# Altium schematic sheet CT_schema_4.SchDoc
size 205 x 258 mm
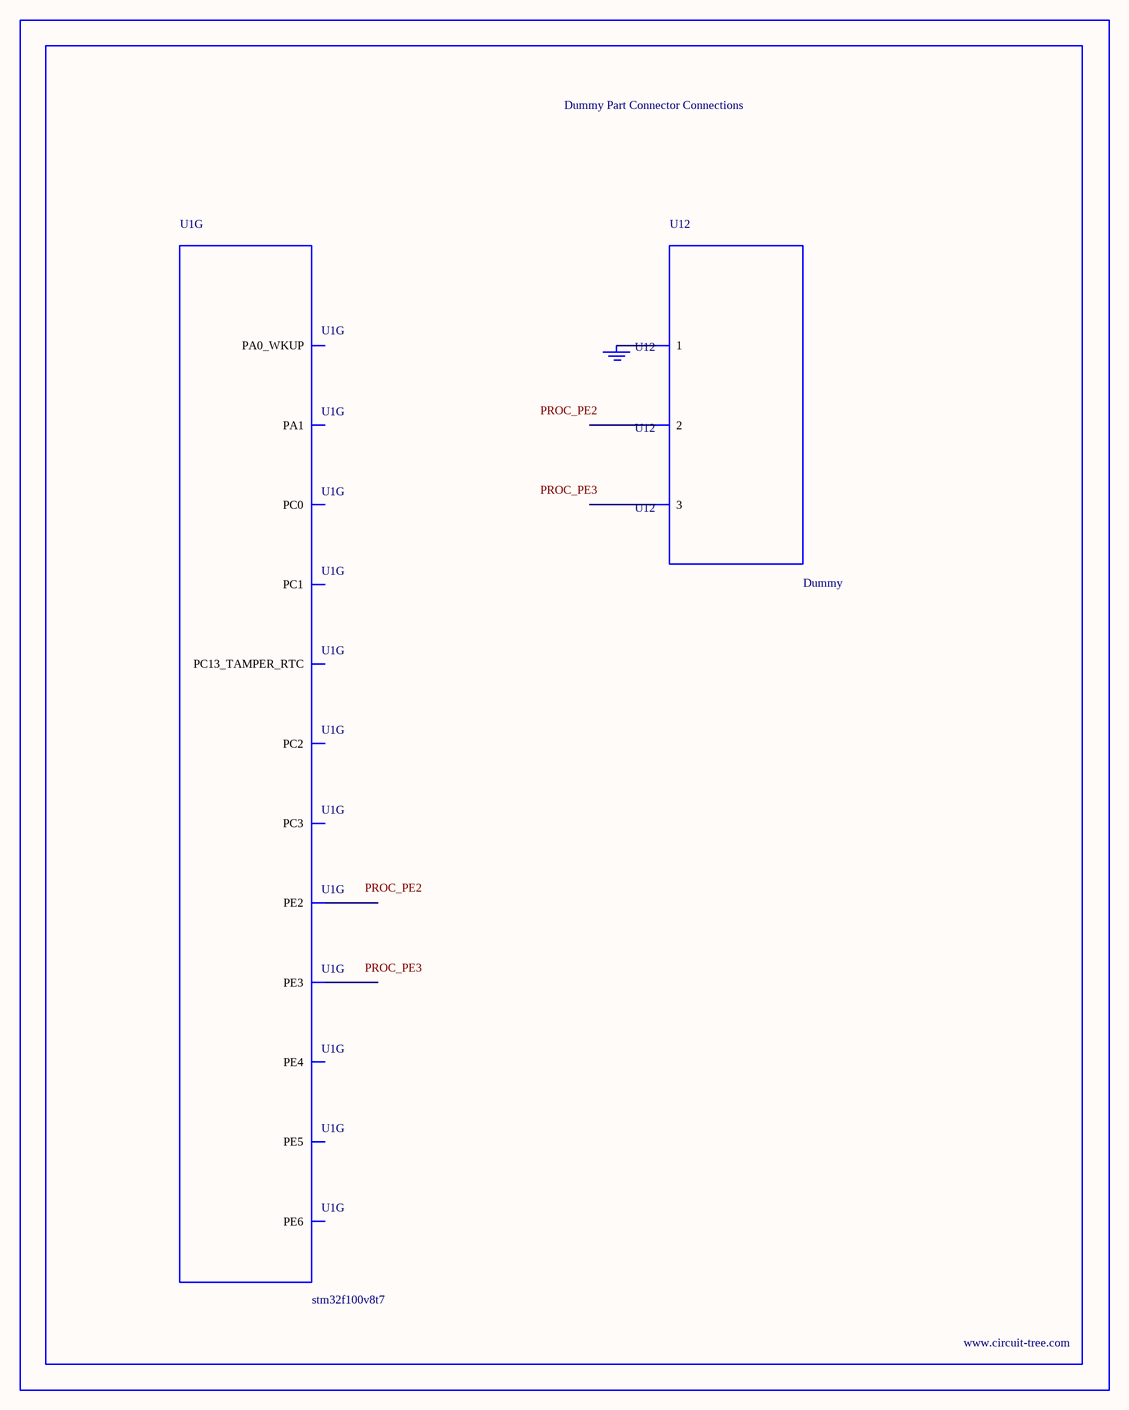
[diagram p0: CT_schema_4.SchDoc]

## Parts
BORDER3  (no value)
GND_INSTANCE_3_0  (no value)
U1  stm32f100v8t7  [LQFP100]  (part G of 7)
U12  Dummy  [DUMMY_PACKAGE_125]

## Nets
NetGND_INSTANCE_3_0_0: GND_INSTANCE_3_0.0(GND) U12.1

Not connected (* = marked no-connect by the designer): U1 1(PE2) 2(PE3) 3(PE4) 4(PE5) 5(PE6) 7(PC13_TAMPER_RTC) 15(PC0) 16(PC1) 17(PC2) 18(PC3) 23(PA0_WKUP) 24(PA1); U12 2 3

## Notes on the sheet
- Labels drawn without touching a wire or pin: PROC_PE2, PROC_PE3

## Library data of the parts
BORDER3 = BORDER_PAGE3
GND_INSTANCE_3_0 = GND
